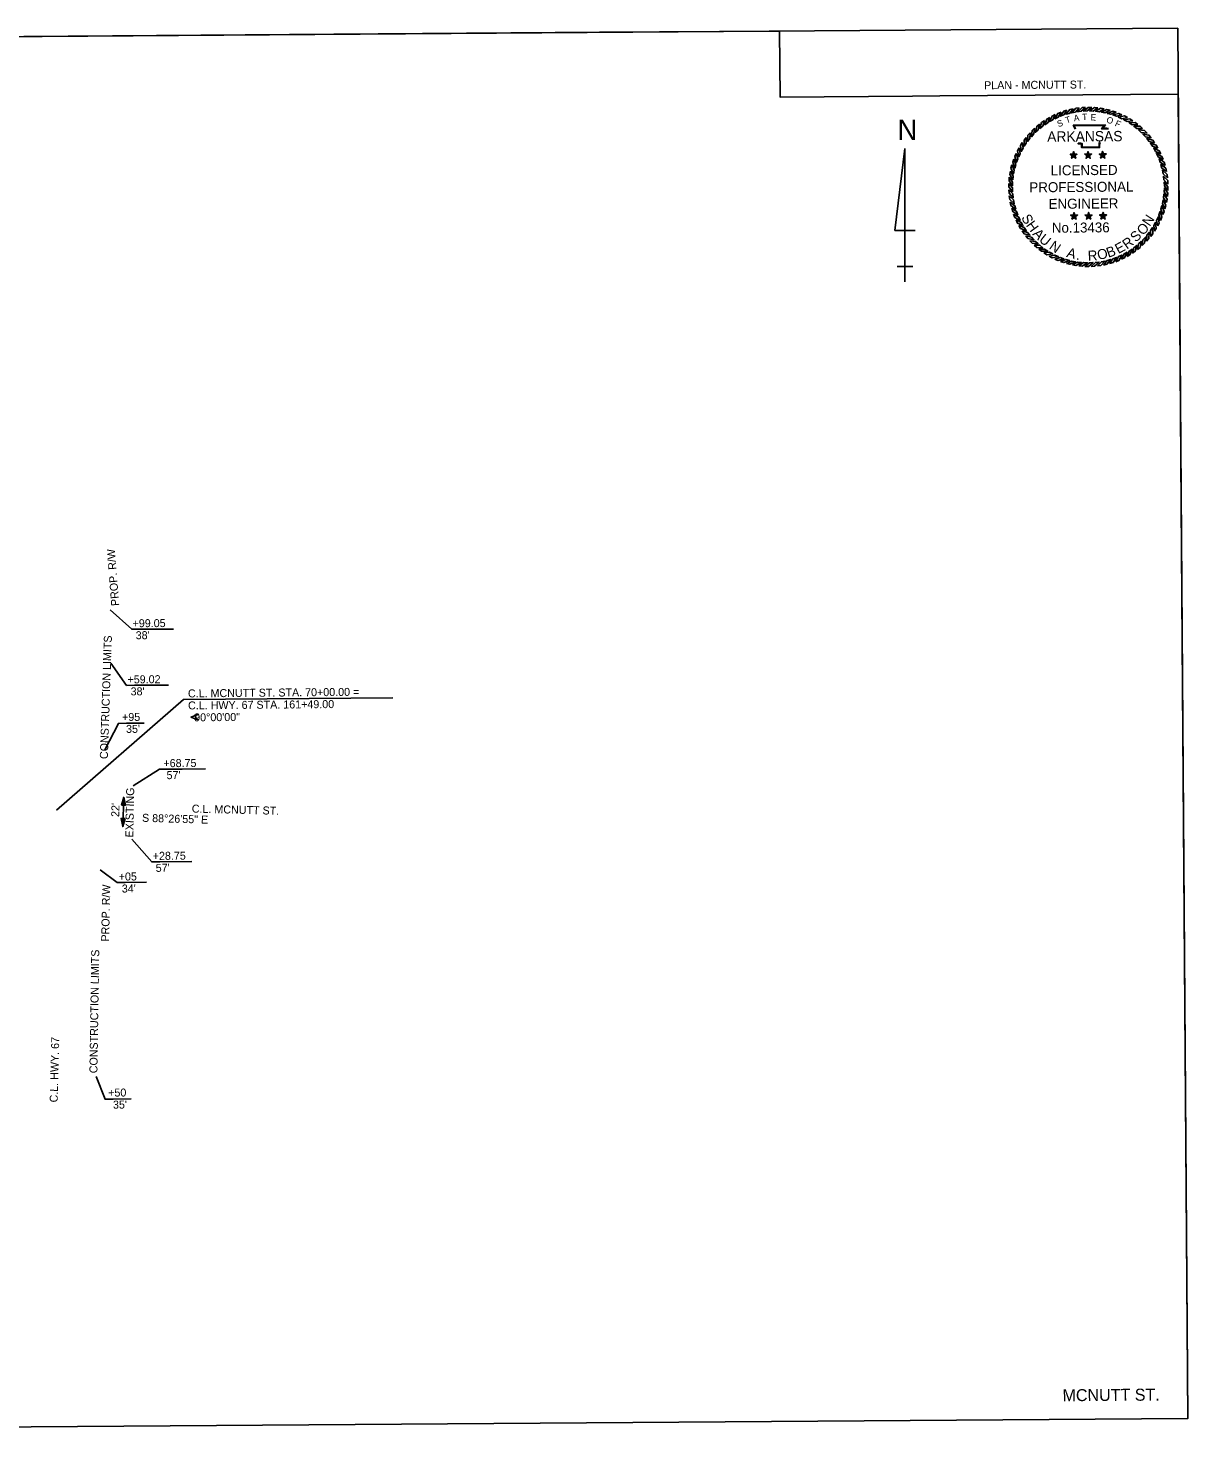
# Model space of a CAD drawing. Extents: x 991791 to 993394, y 1844434 to 1845488.
import ezdxf

# ---------------------------------------------------------------- set-up
doc = ezdxf.new("R2010")
doc.units = 0
for name, color, linetype in [('56', 7, 'Continuous'), ('63', 7, 'Continuous'), ('8', 7, 'Continuous'), ('G-ANNO-SYMB', 7, 'Continuous'), ('G-ANNO-TEXT', 7, 'Continuous'), ('G-Border-Sheet', 7, 'Continuous'), ('G-No Plot-Border-2', 7, 'Continuous'), ('R_Draft', 7, 'Continuous')]:
    doc.layers.add(name, color=color, linetype=linetype)

msp = doc.modelspace()

# ---------------------------------------------------------------- linework, layer by layer
at = {"layer": '56'}
for p in [(992651.8, 1844973.4), (992651.9, 1844969.6)]:
    msp.add_line(p, (992646.4, 1844971.4), dxfattribs=at)
msp.add_arc((992646.4, 1844971.4), 3.74, 326.2335, 35.3281, dxfattribs=at)
at = {"layer": '63'}
for p, q in [((993181.6, 1845397.8), (993173.9, 1845336.3)), ((993181.6, 1845297.8), (993181.6, 1845397.8)), ((993181.6, 1845397.8), (993181.6, 1845320.9)), ((993173.9, 1845336.3), (993189.3, 1845336.3)), ((993181.6, 1845297.8), (993181.6, 1845320.9)), ((993181.6, 1845309.3), (993175.8, 1845309.3)), ((993175.8, 1845309.3), (993187.4, 1845309.3)), ((993181.6, 1845297.8), (993181.6, 1845309.3))]:
    msp.add_line(p, q, dxfattribs=at)
at = {"layer": '8'}
msp.add_lwpolyline([(992545.7, 1844901.9), (992640.8, 1844984.7), (992797.7, 1844985.9)], dxfattribs=at)
at = {"layer": 'G-ANNO-SYMB'}
for points in [[(993290.1, 1845421.2), (993287.8, 1845419.9), (993286.3, 1845415.7), (993288.6, 1845417.2)], [(993294.2, 1845423.4), (993291.9, 1845422.2), (993290, 1845418.1), (993292.4, 1845419.4)], [(993298.6, 1845425.1), (993296.2, 1845424.2), (993294, 1845420.2), (993296.5, 1845421.4)], [(993303, 1845426.6), (993300.6, 1845425.8), (993298, 1845422), (993300.6, 1845423)], [(993307.6, 1845427.6), (993305.1, 1845427.1), (993302.3, 1845423.5), (993304.9, 1845424.2)], [(993312.2, 1845428.4), (993309.7, 1845428), (993306.6, 1845424.6), (993309.3, 1845425.2)], [(993316.9, 1845428.7), (993314.3, 1845428.6), (993311, 1845425.4), (993313.7, 1845425.8)], [(993321.6, 1845428.7), (993319, 1845428.7), (993315.4, 1845425.9), (993318.2, 1845426)], [(993326.2, 1845428.3), (993323.7, 1845428.6), (993319.9, 1845426), (993322.7, 1845425.9)], [(993330.9, 1845427.6), (993328.3, 1845428), (993324.4, 1845425.8), (993327.1, 1845425.4)], [(993335.4, 1845426.5), (993332.9, 1845427.1), (993328.8, 1845425.2), (993331.5, 1845424.6)], [(993339.9, 1845425), (993337.4, 1845425.8), (993333.2, 1845424.2), (993335.8, 1845423.5)], [(993344.2, 1845423.2), (993341.8, 1845424.2), (993337.4, 1845423), (993340, 1845422)], [(993348.4, 1845421), (993346.1, 1845422.3), (993341.6, 1845421.4), (993344.1, 1845420.2)], [(993352.3, 1845418.6), (993350.2, 1845420), (993345.6, 1845419.4), (993348.1, 1845418.1)], [(993275.4, 1845409.7), (993273.7, 1845407.8), (993273.5, 1845403.2), (993275.2, 1845405.4)], [(993278.7, 1845413), (993276.8, 1845411.3), (993276.3, 1845406.7), (993278.2, 1845408.8)], [(993282.3, 1845416.1), (993280.3, 1845414.4), (993279.4, 1845410), (993281.4, 1845411.8)], [(993286.1, 1845418.8), (993283.9, 1845417.3), (993282.7, 1845412.9), (993284.9, 1845414.7)], [(993356.1, 1845415.8), (993354.1, 1845417.4), (993349.5, 1845417.2), (993351.8, 1845415.6)], [(993359.7, 1845412.8), (993357.8, 1845414.5), (993353.2, 1845414.6), (993355.4, 1845412.9)], [(993363, 1845409.4), (993361.2, 1845411.3), (993356.7, 1845411.8), (993358.7, 1845409.9)], [(993366, 1845405.9), (993364.4, 1845407.9), (993359.9, 1845408.7), (993361.8, 1845406.7)], [(993267.1, 1845398.4), (993265.9, 1845396.2), (993266.8, 1845391.7), (993267.9, 1845394.2)], [(993269.5, 1845402.4), (993268.2, 1845400.2), (993268.7, 1845395.7), (993270.1, 1845398.1)], [(993272.3, 1845406.2), (993270.8, 1845404.1), (993270.9, 1845399.6), (993272.5, 1845401.9)], [(993368.7, 1845402.1), (993367.3, 1845404.2), (993362.9, 1845405.4), (993364.6, 1845403.2)], [(993371.2, 1845398.1), (993369.9, 1845400.3), (993365.6, 1845401.8), (993367.1, 1845399.5)], [(993373.3, 1845393.9), (993372.2, 1845396.2), (993368, 1845398.1), (993369.4, 1845395.7)], [(993263.1, 1845389.9), (993262.3, 1845387.5), (993263.9, 1845383.2), (993264.6, 1845385.9)], [(993264.9, 1845394.2), (993263.9, 1845391.9), (993265.2, 1845387.5), (993266.1, 1845390.1)], [(993308, 1845392.8), (993307.3, 1845393.6), (993305.4, 1845393.6), (993307, 1845392.4)], [(993308, 1845392.8), (993307, 1845392.4), (993306.4, 1845390.5), (993308, 1845391.7)], [(993308, 1845392.8), (993308.6, 1845393.6), (993307.9, 1845395.5), (993307.3, 1845393.6)], [(993308, 1845392.8), (993308.9, 1845392.5), (993310.5, 1845393.6), (993308.6, 1845393.6)], [(993308, 1845392.8), (993308, 1845391.7), (993309.6, 1845390.6), (993308.9, 1845392.5)], [(993318.9, 1845392.8), (993318.2, 1845393.7), (993316.3, 1845393.7), (993317.9, 1845392.5)], [(993318.9, 1845392.8), (993317.9, 1845392.5), (993317.3, 1845390.6), (993318.9, 1845391.8)], [(993318.9, 1845392.8), (993319.5, 1845393.7), (993318.8, 1845395.6), (993318.2, 1845393.7)], [(993318.9, 1845392.8), (993319.9, 1845392.5), (993321.4, 1845393.7), (993319.5, 1845393.7)], [(993318.9, 1845392.8), (993318.9, 1845391.8), (993320.5, 1845390.6), (993319.9, 1845392.5)], [(993329.8, 1845392.9), (993329.1, 1845393.8), (993327.2, 1845393.7), (993328.8, 1845392.6)], [(993329.8, 1845392.9), (993328.8, 1845392.6), (993328.2, 1845390.7), (993329.8, 1845391.9)], [(993329.8, 1845392.9), (993330.4, 1845393.8), (993329.7, 1845395.7), (993329.1, 1845393.8)], [(993329.8, 1845392.9), (993330.8, 1845392.6), (993332.4, 1845393.8), (993330.4, 1845393.8)], [(993329.8, 1845392.9), (993329.8, 1845391.9), (993331.4, 1845390.7), (993330.8, 1845392.6)], [(993375.1, 1845389.5), (993374.1, 1845391.9), (993370.1, 1845394.2), (993371.3, 1845391.6)], [(993376.5, 1845385.1), (993375.8, 1845387.5), (993372, 1845390.1), (993372.9, 1845387.5)], [(993260.6, 1845380.9), (993260.1, 1845378.4), (993262.4, 1845374.4), (993262.7, 1845377.2)], [(993261.7, 1845385.5), (993261, 1845383), (993262.9, 1845378.8), (993263.5, 1845381.6)], [(993377.6, 1845380.5), (993377, 1845383), (993373.4, 1845385.9), (993374.2, 1845383.2)], [(993378.3, 1845375.9), (993378, 1845378.4), (993374.6, 1845381.5), (993375.1, 1845378.8)], [(993378.7, 1845371.2), (993378.5, 1845373.8), (993375.4, 1845377.1), (993375.7, 1845374.4)], [(993259.4, 1845371.6), (993259.4, 1845369.1), (993262.2, 1845365.5), (993262.1, 1845368.3)], [(993259.4, 1845366.9), (993259.6, 1845364.4), (993262.7, 1845361), (993262.3, 1845363.8)], [(993259.8, 1845376.3), (993259.6, 1845373.7), (993262.1, 1845370), (993262.2, 1845372.7)], [(993378.3, 1845361.9), (993378.5, 1845364.4), (993376, 1845368.2), (993375.8, 1845365.5)], [(993378.6, 1845366.5), (993378.7, 1845369.1), (993375.9, 1845372.7), (993376, 1845369.9)], [(993259.8, 1845362.3), (993260.1, 1845359.7), (993263.5, 1845356.6), (993262.9, 1845359.4)], [(993260.5, 1845357.6), (993261, 1845355.1), (993264.6, 1845352.3), (993263.9, 1845355)], [(993376.4, 1845352.7), (993377, 1845355.2), (993375.1, 1845359.3), (993374.6, 1845356.6)], [(993377.5, 1845357.3), (993378, 1845359.8), (993375.7, 1845363.8), (993375.4, 1845361)], [(993261.6, 1845353.1), (993262.3, 1845350.6), (993266.1, 1845348.1), (993265.2, 1845350.7)], [(993263, 1845348.6), (993263.9, 1845346.2), (993267.9, 1845344), (993266.8, 1845346.5)], [(993308.3, 1845347.1), (993307.7, 1845347.9), (993305.7, 1845347.9), (993307.3, 1845346.8)], [(993308.3, 1845347.1), (993307.3, 1845346.8), (993306.7, 1845344.9), (993308.3, 1845346)], [(993308.3, 1845347.1), (993308.9, 1845347.9), (993308.3, 1845349.8), (993307.7, 1845347.9)], [(993308.3, 1845347.1), (993309.3, 1845346.8), (993310.9, 1845347.9), (993308.9, 1845347.9)], [(993308.3, 1845347.1), (993308.3, 1845346), (993309.9, 1845344.9), (993309.3, 1845346.8)], [(993319.2, 1845347.2), (993318.6, 1845348), (993316.6, 1845348), (993318.2, 1845346.8)], [(993319.2, 1845347.2), (993318.2, 1845346.8), (993317.6, 1845344.9), (993319.2, 1845346.1)], [(993319.2, 1845347.2), (993319.8, 1845348), (993319.2, 1845349.9), (993318.6, 1845348)], [(993319.2, 1845347.2), (993320.2, 1845346.8), (993321.8, 1845348), (993319.8, 1845348)], [(993319.2, 1845347.2), (993319.2, 1845346.1), (993320.8, 1845345), (993320.2, 1845346.8)], [(993330.1, 1845347.2), (993329.5, 1845348.1), (993327.5, 1845348.1), (993329.1, 1845346.9)], [(993330.1, 1845347.2), (993329.1, 1845346.9), (993328.5, 1845345), (993330.1, 1845346.2)], [(993330.1, 1845347.2), (993330.7, 1845348.1), (993330.1, 1845350), (993329.5, 1845348.1)], [(993330.1, 1845347.2), (993331.1, 1845346.9), (993332.7, 1845348.1), (993330.7, 1845348.1)], [(993330.1, 1845347.2), (993330.1, 1845346.2), (993331.7, 1845345), (993331.1, 1845346.9)], [(993371, 1845339.8), (993372.2, 1845342), (993371.3, 1845346.5), (993370.1, 1845344)], [(993373.1, 1845343.9), (993374.2, 1845346.3), (993372.9, 1845350.7), (993371.9, 1845348.1)], [(993374.9, 1845348.3), (993375.8, 1845350.7), (993374.2, 1845355), (993373.4, 1845352.3)], [(993264.8, 1845344.3), (993265.9, 1845342), (993270, 1845340.1), (993268.7, 1845342.5)], [(993266.9, 1845340.1), (993268.2, 1845337.9), (993272.5, 1845336.3), (993270.9, 1845338.6)], [(993269.3, 1845336.1), (993270.8, 1845334), (993275.2, 1845332.8), (993273.5, 1845335)], [(993362.7, 1845328.4), (993364.4, 1845330.4), (993364.6, 1845334.9), (993362.9, 1845332.8)], [(993365.8, 1845332), (993367.3, 1845334), (993367.1, 1845338.6), (993365.6, 1845336.3)], [(993368.5, 1845335.8), (993369.9, 1845337.9), (993369.4, 1845342.5), (993368, 1845340.1)], [(993272.1, 1845332.3), (993273.7, 1845330.3), (993278.2, 1845329.4), (993276.3, 1845331.5)], [(993275.1, 1845328.7), (993276.9, 1845326.9), (993281.4, 1845326.4), (993279.4, 1845328.2)], [(993278.4, 1845325.4), (993280.3, 1845323.7), (993284.9, 1845323.5), (993282.7, 1845325.3)], [(993352, 1845319.4), (993354.1, 1845320.8), (993355.3, 1845325.2), (993353.2, 1845323.5)], [(993355.8, 1845322.1), (993357.8, 1845323.7), (993358.7, 1845328.2), (993356.6, 1845326.3)], [(993359.4, 1845325.1), (993361.2, 1845326.9), (993361.8, 1845331.5), (993359.9, 1845329.4)], [(993281.9, 1845322.4), (993284, 1845320.8), (993288.6, 1845321), (993286.2, 1845322.5)], [(993285.7, 1845319.6), (993287.9, 1845318.2), (993292.4, 1845318.8), (993290, 1845320.1)], [(993289.7, 1845317.1), (993292, 1845315.9), (993296.5, 1845316.8), (993293.9, 1845318)], [(993293.9, 1845315), (993296.2, 1845314), (993300.6, 1845315.2), (993298, 1845316.2)], [(993298.2, 1845313.2), (993300.6, 1845312.3), (993304.9, 1845313.9), (993302.2, 1845314.7)], [(993330.5, 1845310.5), (993333, 1845311.1), (993335.8, 1845314.7), (993333.1, 1845313.9)], [(993335, 1845311.6), (993337.5, 1845312.4), (993340, 1845316.2), (993337.4, 1845315.2)], [(993339.5, 1845313), (993341.9, 1845314), (993344.1, 1845318), (993341.6, 1845316.8)], [(993343.8, 1845314.8), (993346.1, 1845315.9), (993348, 1845320.1), (993345.6, 1845318.7)], [(993348, 1845316.9), (993350.2, 1845318.2), (993351.8, 1845322.5), (993349.5, 1845321)], [(993302.6, 1845311.7), (993305.1, 1845311.1), (993309.3, 1845313), (993306.6, 1845313.5)], [(993307.2, 1845310.6), (993309.7, 1845310.2), (993313.7, 1845312.4), (993311, 1845312.7)], [(993311.8, 1845309.9), (993314.4, 1845309.6), (993318.2, 1845312.2), (993315.4, 1845312.3)], [(993316.5, 1845309.5), (993319.1, 1845309.4), (993322.6, 1845312.3), (993319.9, 1845312.2)], [(993321.2, 1845309.5), (993323.7, 1845309.6), (993327.1, 1845312.7), (993324.3, 1845312.4)], [(993325.8, 1845309.8), (993328.4, 1845310.2), (993331.5, 1845313.5), (993328.8, 1845313)]]:
    msp.add_lwpolyline(points, close=True, dxfattribs=at)
for points in [[(993309.2, 1845412.3), (993307.7, 1845415.3), (993331.8, 1845415.5), (993329.8, 1845413), (993331.5, 1845413), (993332.8, 1845413), (993334.2, 1845412.9)], [(993309.5, 1845412.5), (993308.3, 1845414.9), (993331, 1845415.1), (993329, 1845412.6), (993331.5, 1845412.6), (993332.8, 1845412.6), (993334.1, 1845412.5)], [(993328.1, 1845402.4), (993327.7, 1845402), (993327.6, 1845401.5), (993327.4, 1845400.3), (993327.5, 1845398.6), (993314, 1845398.5), (993314, 1845400.8), (993314, 1845401.3), (993313.5, 1845401.4), (993311.5, 1845401.4), (993311.2, 1845401.9)], [(993327.9, 1845402.7), (993327.4, 1845402.3), (993327.2, 1845401.6), (993327.1, 1845400.3), (993327.1, 1845399), (993314.4, 1845398.9), (993314.4, 1845400.8), (993314.4, 1845401.6), (993313.5, 1845401.8), (993311.8, 1845401.8), (993311.5, 1845402.1)]]:
    msp.add_lwpolyline(points, dxfattribs=at)
at = {"layer": 'G-Border-Sheet'}
for p in [(991790.7, 1845476.4), (993389.8, 1844967)]:
    msp.add_line(p, (993386, 1845488.1), dxfattribs=at)
msp.add_lwpolyline([(993389.8, 1844967), (993393.6, 1844445.8), (991798.3, 1844434.2), (991794.5, 1844955.3)], dxfattribs=at)
at = {"layer": 'G-No Plot-Border-2'}
msp.add_lwpolyline([(991798.3, 1844434.2), (991790.7, 1845476.4), (992952.6, 1845485), (992952.6, 1845485), (993087.6, 1845485.9), (993088, 1845436.4), (993187.3, 1845437.1), (993207.8, 1845437.3), (993386.3, 1845438.6), (993393.6, 1844445.8)], close=True, dxfattribs=at)
at = {"layer": 'R_Draft'}
for p, q in [((992633.4, 1845037.6), (992608, 1845037.4)), ((992629.6, 1844995.6), (992604.2, 1844995.4)), ((992611.4, 1844967), (992598, 1844966.9)), ((992657.4, 1844932.7), (992639.8, 1844932.6)), ((992596, 1844911.5), (992595.3, 1844889.5)), ((992647, 1844863.2), (992623.1, 1844863)), ((992613, 1844847.7), (992597.2, 1844847.6)), ((992601.5, 1844685.3), (992588.1, 1844685.2))]:
    msp.add_line(p, q, dxfattribs=at)
for points in [[(992586, 1845052.1), (992602, 1845037.4), (992608, 1845037.4)], [(992586.3, 1845012.1), (992598.2, 1844995.3), (992604.2, 1844995.4)], [(992581.9, 1844946.9), (992592, 1844966.8), (992598, 1844966.9)], [(992603.2, 1844920.1), (992622.9, 1844932.5), (992639.8, 1844932.6)], [(992602.1, 1844880.1), (992617.1, 1844863), (992623.1, 1844863)], [(992578.5, 1844857), (992591.2, 1844847.5), (992597.2, 1844847.6)], [(992575.3, 1844702), (992582.1, 1844685.1), (992588.1, 1844685.2)]]:
    msp.add_lwpolyline(points, dxfattribs=at)
for points in [[(992594.3, 1844905.6), (992596, 1844911.5), (992597.3, 1844905.5)], [(992597, 1844895.5), (992595.3, 1844889.5), (992594, 1844895.6)]]:
    msp.add_lwpolyline(points, close=True, dxfattribs=at)

# ---------------------------------------------------------------- texts
at = {"layer": '56'}
for s, p in [('C.L. MCNUTT ST. STA. 70+00.00 = ', (992644.2, 1844986.3)), ('C.L. HWY. 67 STA. 161+49.00', (992644.3, 1844977.3)), ('  90%%D00\'00"', (992644.4, 1844968.3))]:
    msp.add_text(s, height=6, rotation=0.5512, dxfattribs=at).set_placement(p)
at = {"layer": '63'}
msp.add_text('N', height=15.4, rotation=0, dxfattribs=at).set_placement((993176, 1845404.2))
at = {"layer": 'G-ANNO-SYMB'}
for s, height, rotation, p in [('S', 4.75, 20.192, (993296.6, 1845413.8)), ('T', 4.75, 17.3209, (993302.6, 1845416.6)), ('A', 4.75, 9.0982, (993308.4, 1845418.1)), ('T', 4.75, 1.8983, (993314.5, 1845419.1)), ('E', 4.75, 357.0915, (993320.6, 1845419)), ('O', 4.75, 341.6412, (993332.1, 1845417.5)), ('F', 4.75, 335.7823, (993338.5, 1845415)), ('ARKANSAS', 7.75, 0.4194, (993288.2, 1845402.9)), ('LICENSED', 7.5, 0.4194, (993290.8, 1845377.7)), ('PROFESSIONAL', 7.5, 0.4194, (993274.8, 1845365)), ('ENGINEER', 7.5, 0.4194, (993289.2, 1845352.6)), ('S', 7.5, 298.5831, (993268.5, 1845346.1)), ('N', 7.5, 56.5201, (993365, 1845339)), ('H', 7.5, 306.0385, (993272, 1845340.3)), ('A', 7.5, 313.8667, (993276.8, 1845333.5)), ('No.13436', 7.47, 0.4194, (993291.7, 1845334.7)), ('S', 7.5, 43.9073, (993354.7, 1845327.2)), ('O', 7.5, 45.1952, (993359.8, 1845332.2)), ('U', 7.5, 321.3221, (993281.5, 1845328.6)), ('N', 7.5, 325.3521, (993289.1, 1845323.1)), ('B', 7.5, 19.3045, (993334, 1845315.9)), ('E', 7.5, 28.2509, (993341.5, 1845318.7)), ('R', 7.5, 36.0791, (993347.9, 1845322)), ('A', 7.5, 343.5185, (993302.2, 1845316.7)), ('.', 7.5, 351.7195, (993309.6, 1845314.6)), ('R', 7.5, 3.6481, (993318.8, 1845313.7)), ('O', 7.5, 11.8491, (993326.5, 1845314.3))]:
    msp.add_text(s, height=height, rotation=rotation, dxfattribs=at).set_placement(p)
at = {"layer": 'G-ANNO-TEXT'}
for s, height, p in [('PLAN - MCNUTT ST.', 6, (993240.9, 1845442.3)), ('MCNUTT ST.', 9, (993299.7, 1844458.6))]:
    msp.add_text(s, height=height, rotation=0.4194, dxfattribs=at).set_placement(p)
at = {"layer": 'R_Draft'}
for s, rotation, p in [('PROP. R/W', 94.3895, (992592.7, 1845055.1)), ('+99.05', 0.4194, (992602.7, 1845038.9)), ('CONSTRUCTION LIMITS', 88.0753, (992584.1, 1844940)), (" 38'", 0.4194, (992602.8, 1845029.9)), ('+59.02', 0.4194, (992598.9, 1844996.8)), (" 38'", 0.4194, (992599, 1844987.8)), ('+95', 0.4194, (992594.8, 1844968.6)), ("35'", 0.4194, (992597.8, 1844959.7)), ('+68.75', 0.4194, (992625.8, 1844934)), (" 57'", 0.4194, (992625.9, 1844925)), ('EXISTING', 88.8746, (992603.2, 1844881.3)), ("22'", 88.2286, (992592.6, 1844896.6)), ('C.L. MCNUTT ST.', 358.5071, (992647, 1844900)), ('S 88%%d26\'55" E', 358.3279, (992609.7, 1844893.1)), ('+28.75', 0.4194, (992617.8, 1844864.5)), (" 57'", 0.4194, (992617.8, 1844855.5)), ('+05', 0.4194, (992592.3, 1844849)), ('PROP. R/W', 88.8183, (992585.1, 1844803.2)), (" 34'", 0.4194, (992592.4, 1844840)), ('CONSTRUCTION LIMITS', 89.1091, (992576.3, 1844704.5)), ('C.L. HWY. 67', 88.5071, (992546.5, 1844682.6)), ('+50', 0.4194, (992584.4, 1844687)), ("35'", 0.4194, (992588, 1844678))]:
    msp.add_text(s, height=6, rotation=rotation, dxfattribs=at).set_placement(p)

doc.saveas('drawing.dxf')
